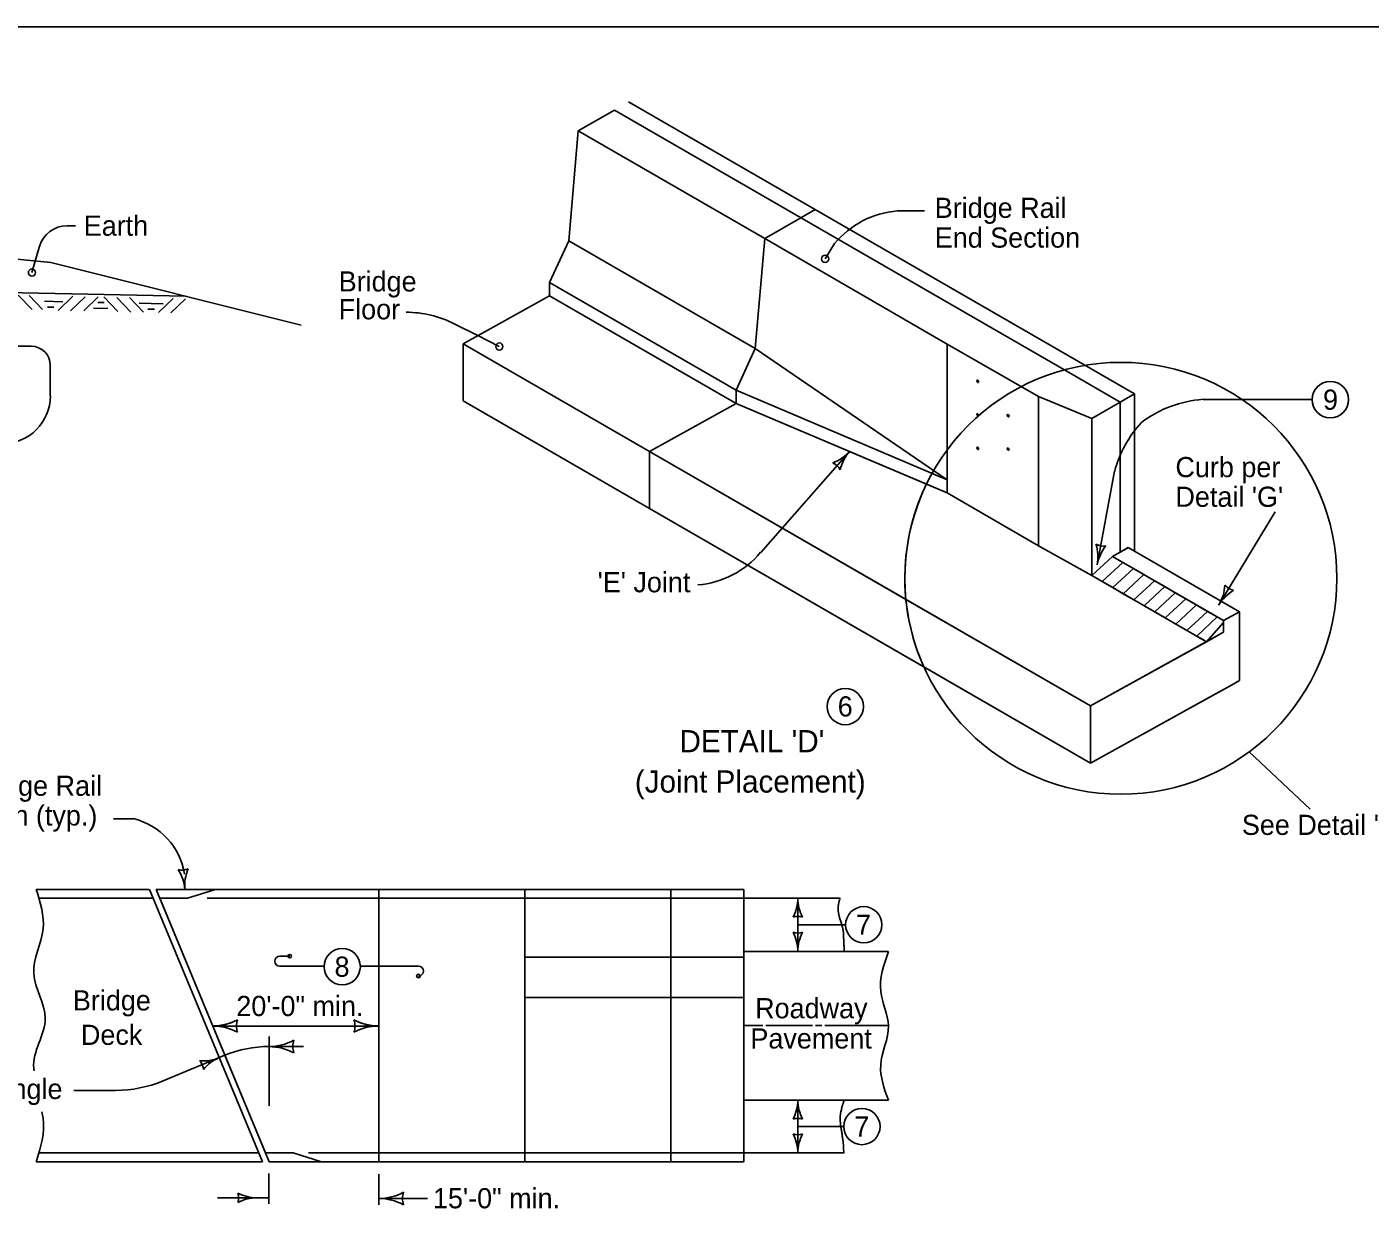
# Model space of a CAD drawing. Extents: x 10130 to 81668, y 5440 to 21644.
# Drawn here: x 18491 to 19823, y 6374 to 7554 of the extents above; entities that cross this region are included whole.
import ezdxf

# ---------------------------------------------------------------- set-up
doc = ezdxf.new("R2010")
doc.units = 0
for name, color, linetype in [('Cell', 7, 'Continuous'), ('dsnCellElements', 7, 'Continuous'), ('dsnStdBlockModified', 7, 'Continuous'), ('dsnStdBlockNotModified', 7, 'Continuous'), ('dsnStdBorder', 7, 'Continuous'), ('Level 5', 7, 'Continuous')]:
    doc.layers.add(name, color=color, linetype=linetype)

msp = doc.modelspace()

# ---------------------------------------------------------------- linework, layer by layer
at = {"layer": 'Cell'}
msp.add_lwpolyline([(17403.2, 7554.1), (20538.2, 7554.1), (20538.2, 5544.1), (17403.2, 5544.1)], close=True, dxfattribs=at)
at = {"layer": 'dsnCellElements'}
for centre in [(19282.5, 7324), (18495.9, 7310.4), (18959.4, 7237)]:
    msp.add_circle(centre, 3.54, dxfattribs=at)
at = {"layer": 'dsnStdBlockModified'}
for p, q in [((19129.6, 6689.8), (18984.7, 6689.8)), ((18984.7, 6689.8), (18984.7, 6631.2)), ((19129.6, 6631.2), (19129.6, 6689.8)), ((19202, 6689.8), (19129.6, 6689.8)), ((19129.6, 6689.8), (19129.6, 6631.2)), ((19202, 6631.2), (19202, 6689.8)), ((19129.6, 6631.2), (18984.7, 6631.2)), ((18984.7, 6631.2), (18984.7, 6591.2)), ((18984.7, 6631.2), (19129.6, 6631.2)), ((19129.6, 6591.2), (19129.6, 6631.2)), ((19129.6, 6631.2), (19129.6, 6631.2)), ((19202, 6631.2), (19129.6, 6631.2)), ((19129.6, 6631.2), (19129.6, 6591.2)), ((19129.6, 6631.2), (19202, 6631.2)), ((19202, 6591.2), (19202, 6631.2)), ((18984.7, 6591.2), (18984.7, 6437)), ((18984.7, 6591.2), (19129.6, 6591.2)), ((19129.6, 6437), (19129.6, 6591.2)), ((19129.6, 6591.2), (19129.6, 6437)), ((19202, 6591.2), (19129.6, 6591.2)), ((19129.6, 6591.2), (19202, 6591.2)), ((19202, 6437), (19202, 6591.2)), ((18984.7, 6437), (19129.6, 6437)), ((19129.6, 6437), (19202, 6437))]:
    msp.add_line(p, q, dxfattribs=at)
for points in [[(18839.8, 6698.5), (18984.7, 6698.5), (18984.7, 6689.8), (18864.7, 6689.8), (18839.8, 6689.8)], [(19129.6, 6698.4), (19129.6, 6689.8), (18984.7, 6689.8), (18984.7, 6698.5)], [(19202, 6698.4), (19202, 6689.8), (19129.6, 6689.8), (19129.6, 6698.4)], [(18984.7, 6428.1), (18839.8, 6428.1), (18839.8, 6437), (18847, 6437), (18890.3, 6437), (18937.9, 6437), (18984.7, 6436.9)], [(18984.7, 6428.1), (18984.7, 6437), (19129.6, 6437), (19129.6, 6428.1)], [(19202, 6428.1), (19129.6, 6428.1), (19129.6, 6437), (19202, 6437)]]:
    msp.add_lwpolyline(points, close=True, dxfattribs=at)
msp.add_lwpolyline([(19129.6, 6591.2), (19129.6, 6591.2), (18984.7, 6591.2)], dxfattribs=at)
at = {"layer": 'dsnStdBlockNotModified'}
for centre in [(18751.5, 6632.2), (18879.2, 6612.5)]:
    msp.add_circle(centre, 1.78, dxfattribs=at)
for centre, radius, start, end in [((19275.1, 7161.3), 42.5, 290.5435, 318.616), ((19338.9, 7105.1), 42.5, 138.616, 166.6885), ((19283.5, 7106.4), 16.4, 30.8827, 66.3494), ((19558.9, 7055.5), 16.4, 241.782, 277.2487), ((19510.6, 7028.2), 42.5, 349.5153, 17.5878), ((19594.2, 7012.8), 42.5, 141.4428, 169.5153), ((19636.5, 7002.7), 42.5, 328.7108, 356.7833), ((19709.1, 6958.5), 42.5, 120.6383, 148.7108), ((19691.3, 7011.1), 16.4, 220.9775, 256.4442), ((18644.8, 6734), 16.4, 256.6331, 292.0998), ((18605.1, 6695.2), 42.5, 4.3665, 32.439), ((18689.9, 6701.7), 42.5, 156.294, 184.3665)]:
    msp.add_arc(centre, radius, start, end, dxfattribs=at)
at = {"layer": 'dsnStdBorder'}
for p, q in [((19087.6, 7479.7), (19589.4, 7190)), ((19258.5, 7364.7), (19272.6, 7372.9)), ((19354, 7371.6), (19380.9, 7371.6)), ((18539.1, 7356.8), (18530.7, 7356.8)), ((19213.2, 7234.9), (19028.2, 7341.7)), ((18402.4, 7331.6), (18514.7, 7320.4)), ((18503.5, 7336.4), (18495.9, 7310.4)), ((19282.5, 7324), (19291.8, 7339.2)), ((18514.7, 7320.4), (18763, 7258.3)), ((19009.3, 7300.4), (19009.3, 7287.3)), ((19194.3, 7193.6), (19009.3, 7300.4)), ((18470.5, 7290.5), (18648.4, 7287)), ((18482.2, 7288), (18496.1, 7273.6)), ((18493.1, 7287.6), (18506.5, 7273.7)), ((18536.3, 7286.8), (18521.9, 7272.9)), ((18548.7, 7286.3), (18534.3, 7272.4)), ((18561.7, 7286.3), (18547.3, 7272.4)), ((18567.2, 7286.2), (18581, 7271.7)), ((18580.2, 7285.7), (18594, 7271.2)), ((18592.6, 7285.6), (18606.5, 7271.2)), ((18635.8, 7284.8), (18621.4, 7270.9)), ((18648.3, 7284.3), (18633.8, 7270.4)), ((18914.7, 7259.6), (18938.1, 7247.8)), ((18938.1, 7247.8), (18959.4, 7237)), ((18495.2, 7237.3), (18470.5, 7237.3)), ((19403.7, 7239.5), (19403.7, 7091.7)), ((18514.1, 7218.4), (18514.1, 7188)), ((19194.3, 7180.5), (19108.5, 7132.9)), ((19194.3, 7180.5), (19108.5, 7132.9)), ((19383, 7100.4), (19194.3, 7180.5)), ((19403.7, 7091.7), (19194.3, 7180.5)), ((19494.2, 7187.3), (19494.2, 7039.4)), ((19575.2, 7181.8), (19589.4, 7190)), ((19589.4, 7190), (19589.4, 7033.9)), ((19657.4, 7184.6), (19765.5, 7184.6)), ((19547, 7009.8), (19547, 7165.5)), ((19108.5, 7132.9), (19108.5, 7076.3)), ((19362.6, 6986.2), (19108.5, 7132.9)), ((19108.5, 7132.9), (19108.5, 7076.3)), ((19108.5, 7132.9), (19362.6, 6986.2)), ((19108.5, 7132.9), (19545.7, 6880.4)), ((19307, 7133.2), (19218.6, 7032.8)), ((19403.7, 7091.7), (19383, 7100.4)), ((19569.6, 7113.5), (19552.4, 7020.5)), ((19494.2, 7039.4), (19403.7, 7091.7)), ((19494.2, 7039.4), (19403.7, 7091.7)), ((19108.5, 7076.3), (19545.7, 6823.8)), ((19108.5, 7076.3), (19380.4, 6919.3)), ((19545.7, 6823.8), (19108.5, 7076.3)), ((19672.8, 6980.6), (19728.9, 7073)), ((19547, 7009.8), (19494.2, 7039.4)), ((19547, 7009.8), (19494.2, 7039.4)), ((19693.3, 6973.9), (19583.1, 7037.5)), ((19693.3, 6973.9), (19583.1, 7037.5)), ((19567.4, 7028.8), (19547, 7009.8)), ((19567.4, 7028.8), (19547, 7009.8)), ((19557.4, 7003.8), (19577.8, 7022.8)), ((19577.8, 7022.8), (19557.4, 7003.8)), ((19577.8, 7022.8), (19557.4, 7003.8)), ((19575.2, 7033.1), (19567.4, 7028.8)), ((19577.8, 7022.8), (19567.4, 7028.8)), ((19567.4, 7028.8), (19577.8, 7022.8)), ((19677.6, 6965.2), (19567.4, 7028.8)), ((19588.2, 7016.7), (19577.8, 7022.8)), ((19577.8, 7022.8), (19588.2, 7016.7)), ((19557.4, 7003.8), (19547, 7009.8)), ((19547, 7009.8), (19557.4, 7003.8)), ((19660.7, 6944.2), (19547, 7009.8)), ((19567.8, 6997.8), (19588.2, 7016.7)), ((19588.2, 7016.7), (19567.8, 6997.8)), ((19588.2, 7016.7), (19567.8, 6997.8)), ((19578.2, 6991.8), (19598.6, 7010.7)), ((19598.6, 7010.7), (19578.2, 6991.8)), ((19598.6, 7010.7), (19578.2, 6991.8)), ((19598.6, 7010.7), (19588.2, 7016.7)), ((19588.2, 7016.7), (19598.6, 7010.7)), ((19609, 7004.7), (19598.6, 7010.7)), ((19598.6, 7010.7), (19609, 7004.7)), ((19557.4, 7003.8), (19567.8, 6997.8)), ((19567.8, 6997.8), (19578.2, 6991.8)), ((19588.6, 6985.8), (19609, 7004.7)), ((19609, 7004.7), (19588.6, 6985.8)), ((19609, 7004.7), (19588.6, 6985.8)), ((19619.3, 6998.8), (19599.2, 6980.2)), ((19362.6, 6986.2), (19545.7, 6880.4)), ((19545.7, 6880.4), (19362.6, 6986.2)), ((19578.2, 6991.8), (19588.6, 6985.8)), ((19588.6, 6985.8), (19609.4, 6973.8)), ((19609.4, 6973.8), (19629.8, 6992.7)), ((19629.8, 6992.7), (19609.4, 6973.8)), ((19629.8, 6992.7), (19609.4, 6973.8)), ((19619.8, 6967.8), (19640.2, 6986.7)), ((19640.2, 6986.7), (19619.8, 6967.8)), ((19640.2, 6986.7), (19619.8, 6967.8)), ((19640.2, 6986.7), (19629.8, 6992.7)), ((19629.8, 6992.7), (19640.2, 6986.7)), ((19650.7, 6980.7), (19630.3, 6961.7)), ((19609.4, 6973.8), (19619.8, 6967.8)), ((19619.8, 6967.8), (19630.3, 6961.7)), ((19661.7, 6974.3), (19641.3, 6955.4)), ((19651, 6949.8), (19671.4, 6968.7)), ((19671.4, 6968.7), (19651, 6949.8)), ((19671.4, 6968.7), (19651, 6949.8)), ((19677.6, 6965.2), (19671.4, 6968.7)), ((19671.4, 6968.7), (19677.6, 6965.2)), ((19685.4, 6969.5), (19677.6, 6965.2)), ((19677.6, 6965.2), (19685.4, 6969.5)), ((19685.4, 6969.5), (19677.6, 6965.2)), ((19693.3, 6973.9), (19685.4, 6969.5)), ((19685.4, 6969.5), (19693.3, 6973.9)), ((19693.3, 6973.9), (19685.4, 6969.5)), ((19693.3, 6905.6), (19693.3, 6973.9)), ((19630.3, 6961.7), (19651, 6949.8)), ((19660.7, 6944.2), (19677.6, 6963.2)), ((19677.6, 6963.2), (19660.7, 6944.2)), ((19660.7, 6944.2), (19677.6, 6963.2)), ((19677.6, 6963.2), (19677.6, 6965.2)), ((19677.6, 6953.5), (19677.6, 6965.2)), ((19677.6, 6953.5), (19677.6, 6963.2)), ((19545.7, 6880.4), (19677.6, 6953.5)), ((19545.7, 6880.4), (19660.7, 6944.2)), ((19660.7, 6944.2), (19545.7, 6880.4)), ((19651, 6949.8), (19657.1, 6946.2)), ((19660.7, 6944.2), (19657.1, 6946.2)), ((19657.1, 6946.2), (19660.7, 6944.2)), ((19677.6, 6953.5), (19660.7, 6944.2)), ((19660.7, 6944.2), (19677.6, 6953.5)), ((19380.4, 6919.3), (19545.7, 6823.8)), ((19650.2, 6881.7), (19685.4, 6901.2)), ((19670.4, 6892.9), (19685.4, 6901.2)), ((19685.4, 6901.2), (19693.3, 6905.6)), ((19693.3, 6905.6), (19685.4, 6901.2)), ((19545.7, 6823.8), (19670.4, 6892.9)), ((19545.7, 6823.8), (19545.7, 6880.4)), ((19703.2, 6834.9), (19763.5, 6778.1)), ((18596.2, 6768.6), (18576.7, 6768.6)), ((18500.2, 6698.5), (18612.3, 6698.5)), ((18503, 6689.8), (18616, 6689.8)), ((18724.4, 6428.1), (18612.4, 6698.5)), ((18731.1, 6428.1), (18619.1, 6698.5)), ((18619.1, 6698.5), (18839.8, 6698.5)), ((18622.6, 6689.8), (18650.2, 6689.8)), ((18650.2, 6689.8), (18677.9, 6698.5)), ((18669.7, 6689.8), (19297.4, 6689.8)), ((18839.8, 6637), (18839.8, 6698.5)), ((18839.8, 6437), (18839.8, 6698.5)), ((18839.8, 6698.5), (19202, 6698.4)), ((18984.7, 6689.7), (18839.8, 6689.8)), ((18984.7, 6428.1), (18984.7, 6698.5)), ((19129.6, 6428.1), (19129.6, 6698.4)), ((19202, 6428.1), (19202, 6698.4)), ((19202, 6437), (19202, 6689.8)), ((19255.4, 6637), (19255.4, 6689.8)), ((19255.4, 6663.4), (19284.9, 6663.4)), ((19284.9, 6663.4), (19302.8, 6663.4)), ((19202, 6637), (19345.3, 6637)), ((18751.5, 6632.2), (18741.7, 6632.2)), ((18785.6, 6622.3), (18741.7, 6622.3)), ((18821.6, 6622.3), (18879.2, 6622.3)), ((18675.1, 6562.9), (18839.8, 6562.9)), ((18816.2, 6562.9), (18698.7, 6562.9)), ((18698.7, 6562.9), (18816.2, 6562.9)), ((18839.8, 6562.9), (18839.8, 6562.9)), ((18839.8, 6562.9), (18839.8, 6495)), ((18731.1, 6552.6), (18731.1, 6483.9)), ((18731.1, 6542.6), (18765.1, 6542.6)), ((18687.3, 6533.9), (18625.9, 6508.4)), ((18578.9, 6499.1), (18537.4, 6499.1)), ((18839.8, 6495), (18839.8, 6437)), ((18839.8, 6428.1), (18839.8, 6495)), ((19202, 6489.5), (19345.3, 6489.5)), ((19255.4, 6436.9), (19255.4, 6489.5)), ((19255.4, 6463.2), (19284.9, 6463.2)), ((19284.9, 6463.2), (19301, 6463.2)), ((18502.9, 6437), (18720.8, 6437)), ((18727.4, 6437), (18755, 6437)), ((18727.4, 6437), (18755, 6437)), ((18755, 6437), (18783.1, 6428.1)), ((18755, 6437), (18783.1, 6428.1)), ((18770.1, 6437), (19301.1, 6437)), ((18839.8, 6437), (18890.3, 6437)), ((18890.3, 6437), (18890.3, 6437)), ((18500.2, 6428.1), (18724.4, 6428.1)), ((18731.1, 6428.1), (18839.8, 6428.1)), ((18783.1, 6428.1), (18839.8, 6428.1)), ((18839.8, 6428.1), (19202, 6428.1)), ((18730.7, 6416.6), (18730.7, 6386.4)), ((18839.8, 6415.8), (18839.8, 6385.7)), ((18679.8, 6392.6), (18730.7, 6392.6)), ((18839.8, 6391.8), (18888.2, 6391.8))]:
    msp.add_line(p, q, dxfattribs=at)
for points in [[(19073.5, 7471.5), (19439.5, 7260.2), (19530, 7208), (19575.2, 7181.8), (19547, 7165.5), (19494.2, 7187.3), (19403.7, 7239.5), (19222.6, 7344.1), (19037.6, 7450.9)], [(19037.6, 7450.9), (19073.5, 7471.5)], [(19009.3, 7300.4), (19028.2, 7341.7), (19037.6, 7450.9)], [(19222.6, 7344.1), (19258.5, 7364.7)], [(19194.3, 7180.5), (19194.3, 7193.6), (19213.2, 7234.9), (19222.6, 7344.1)], [(19009.3, 7287.3), (18923.5, 7239.7)], [(19194.3, 7180.5), (19009.3, 7287.3)], [(18508.5, 7281.9), (18526.6, 7281.5)], [(18511.2, 7276), (18517.7, 7275.9)], [(18557.1, 7275), (18571.3, 7274.7)], [(18561.1, 7280.8), (18567.6, 7280.6)], [(18602.1, 7280), (18626.1, 7279.5)], [(18610.7, 7274), (18617.3, 7273.9)], [(18923.5, 7239.7), (19108.5, 7132.9)], [(18923.5, 7183.1), (18923.5, 7239.7)], [(19194.3, 7193.6), (19403.7, 7104.7), (19213.2, 7234.9)], [(19108.5, 7076.3), (18923.5, 7183.1)], [(19194.3, 7180.5), (19108.5, 7132.9)], [(19575.2, 7181.8), (19575.2, 7033.1)], [(19108.5, 7076.3), (19108.5, 7132.9)], [(19583.1, 7037.5), (19582.3, 7037), (19575.2, 7033.1)], [(19583.1, 7037.5), (19575.2, 7033.1)], [(19575.2, 7033.1), (19567.4, 7028.8)], [(19578.2, 6991.8), (19567.8, 6997.8), (19557.4, 7003.8)], [(19629.8, 6992.7), (19619.3, 6998.8), (19609, 7004.7)], [(19609, 7004.7), (19619.3, 6998.8), (19629.8, 6992.7)], [(19609.4, 6973.8), (19588.6, 6985.8), (19578.2, 6991.8)], [(19671.4, 6968.7), (19661.7, 6974.3), (19640.2, 6986.7)], [(19640.2, 6986.7), (19661.7, 6974.3), (19671.4, 6968.7)], [(19657.1, 6946.2), (19651, 6949.8), (19630.3, 6961.7), (19619.8, 6967.8), (19609.4, 6973.8)], [(19693.3, 6973.9), (19693.3, 6905.6)], [(19677.6, 6965.2), (19677.6, 6963.2), (19677.6, 6953.5)], [(19545.7, 6823.8), (19650.2, 6881.7), (19670.4, 6892.9)], [(18839, 6562.9), (18839.8, 6562.9), (18839.8, 6698.5), (18677.9, 6698.5), (18650.2, 6689.8), (18622.7, 6689.8), (18675.2, 6562.9), (18675.9, 6562.9)], [(18839.8, 6689.8), (18839.8, 6622.3), (18839.8, 6562.9)], [(18984.7, 6436.9), (18984.7, 6563.4), (18984.7, 6689.7)], [(18675.2, 6562.9), (18687.3, 6533.9), (18727.4, 6437)], [(18839.8, 6428.1), (18839.8, 6437), (18839.8, 6489.6), (18839.8, 6562.9)], [(18839.8, 6562.9), (18839.8, 6562.9)], [(19202, 6563.3), (19220.7, 6563.3)], [(19223.8, 6563.3), (19269.9, 6563.3)], [(19273, 6563.3), (19279.1, 6563.3)], [(19282.2, 6563.3), (19345.3, 6563.3)], [(18890.3, 6437), (18937.9, 6437), (18984.7, 6436.9)]]:
    msp.add_lwpolyline(points, dxfattribs=at)
for centre, radius in [((19575.8, 7007.1), 214.2), ((19783.5, 7184.3), 18), ((19302.5, 6879.8), 18), ((19320.8, 6663.4), 18), ((18803.6, 6621.8), 18), ((19319, 6463.2), 18)]:
    msp.add_circle(centre, radius, dxfattribs=at)
for centre, radius, start, end in [((19361.7, 7280.9), 91, 94.8409, 140.1467), ((18530.7, 7328.4), 28.4, 90, 163.739), ((18867, 7165.1), 105.9, 63.2177, 90), ((18495.2, 7218.4), 18.9, 0, 90), ((18466.9, 7188), 47.3, 270, 360), ((19666.3, 7067.5), 117.5, 94.3399, 126.627), ((19683, 7082.5), 117.5, 137.5971, 164.7195), ((19575.8, 7007.1), 214.2, 154.1687, 185.6063), ((19575.8, 7007.1), 214.2, 154.1687, 185.6063), ((19148.7, 7091.2), 91, 274.8409, 320.1467), ((19575.8, 7007.1), 214.2, 185.6063, 204.2018), ((19575.8, 7007.1), 214.2, 185.6063, 204.2018), ((18581.1, 6703.7), 66.7, 8.4828, 76.8823), ((19215.2, 6689.8), 40.2, 331.9275, 360), ((19295.6, 6689.8), 40.2, 180, 208.0725), ((19255.4, 6656.1), 15.5, 72.2666, 107.7334), ((19255.4, 6670.7), 15.5, 252.2666, 287.7333), ((19215.2, 6637), 40.2, 360, 28.0725), ((19295.6, 6637), 40.2, 151.9275, 180), ((18741.7, 6627.2), 4.92, 90, 270), ((18879.2, 6617.4), 4.92, 270, 90), ((18675.1, 6615.2), 52.2, 270, 298.0725), ((18675.1, 6615.2), 52.2, 270.8433, 298.0725), ((18718.9, 6562.9), 20.2, 162.2666, 197.7334), ((18718.9, 6562.9), 20.2, 162.2667, 179.9839), ((18796, 6562.9), 20.2, 342.2666, 17.7334), ((18839.8, 6615.2), 52.2, 241.9275, 270), ((18796, 6562.9), 20.2, 0.0161, 17.7334), ((18839.8, 6615.2), 52.2, 241.9275, 269.1567), ((18675.1, 6510.7), 52.2, 61.9275, 90), ((18675.1, 6510.7), 52.2, 61.9275, 89.8364), ((18718.9, 6562.9), 20.2, 179.9839, 197.7334), ((18839.8, 6510.7), 52.2, 90.0176, 118.0725), ((18796, 6562.9), 20.2, 342.2666, 0.0161), ((18839.8, 6510.7), 52.2, 90, 118.0725), ((18839.8, 6615.2), 52.2, 269.9824, 270), ((18731.1, 6428.1), 114.5, 90, 112.5), ((18731.1, 6594.8), 52.2, 270, 298.0725), ((18731.1, 6594.8), 52.2, 270, 298.0725), ((18731.1, 6490.3), 52.2, 61.9275, 90), ((18731.1, 6490.3), 52.2, 61.9275, 90), ((18774.9, 6542.6), 20.2, 162.2666, 197.7334), ((18774.9, 6542.6), 20.2, 162.2666, 197.7334), ((18666.2, 6568.6), 40.2, 264.4275, 292.5), ((18650.5, 6518.6), 15.5, 4.7666, 40.2333), ((18697, 6494.4), 40.2, 112.5, 140.5725), ((18578.9, 6622), 122.9, 270, 292.5), ((19215.2, 6489.5), 40.2, 331.9275, 360), ((19295.6, 6489.5), 40.2, 180, 208.0725), ((19255.4, 6455.8), 15.5, 72.2666, 107.7334), ((19255.4, 6470.6), 15.5, 252.2666, 287.7333), ((19215.2, 6436.9), 40.2, 360, 28.0725), ((19295.6, 6436.9), 40.2, 151.9275, 180), ((18850.1, 6437), 40.2, 359.9859, 360), ((18685.3, 6392.5), 15.5, 342.2666, 17.7334), ((18719, 6432.7), 40.2, 241.9275, 270), ((18839.8, 6444), 52.2, 270, 298.0725), ((18883.6, 6391.8), 20.2, 162.2666, 197.7334), ((18719, 6352.4), 40.2, 90, 118.0725), ((18839.8, 6339.6), 52.2, 61.9275, 90)]:
    msp.add_arc(centre, radius, start, end, dxfattribs=at)
for centre in [(19433.8, 7202.4), (19433.8, 7169.2), (19464, 7168.4), (19433.8, 7136), (19464, 7135.2)]:
    msp.add_ellipse(centre, major_axis=(0.67, -1.15), ratio=0.57735, dxfattribs=at)
for points in [[(18500.2, 6698.5), (18507, 6659.3), (18497.7, 6614.9), (18509.1, 6570.5), (18497.7, 6521), (18498, 6518.6)], [(19345.3, 6637), (19337.6, 6597.3), (19345.3, 6563.2), (19337.6, 6524), (19345.3, 6489.5)], [(18505.8, 6477.7), (18507, 6471.5), (18500.2, 6428.1)]]:
    msp.add_spline(points, degree=3, dxfattribs=at)
for points in [[(19297.4, 6689.8), (19297.2, 6689.3), (19297, 6688.8), (19296.9, 6688.3), (19296.7, 6687.8), (19296.6, 6687.3), (19296.5, 6686.8), (19296.2, 6685.8), (19296, 6684.8), (19295.8, 6683.8), (19295.6, 6682.8), (19295.5, 6681.8), (19295.5, 6680.8), (19295.4, 6680.3), (19295.4, 6679.8), (19295.4, 6679.3), (19295.4, 6678.8), (19295.4, 6678.3), (19295.5, 6677.8), (19295.5, 6676.9), (19295.6, 6675.9), (19295.8, 6675), (19296, 6674.1), (19296.1, 6673.1), (19296.4, 6672.2), (19296.9, 6670.3), (19297.5, 6668.4), (19298.1, 6666.5), (19298.6, 6664.7), (19299.2, 6662.8), (19299.7, 6660.9), (19300, 6659.9), (19300.2, 6659), (19300.3, 6658), (19300.5, 6657.1), (19300.6, 6656.1), (19300.6, 6655.1), (19300.7, 6653.6), (19300.8, 6652.1), (19300.9, 6650.6), (19300.9, 6649.1), (19301, 6647.6), (19301.1, 6646.1), (19301.2, 6644.6), (19301.2, 6643.1), (19301.3, 6641.5), (19301.4, 6640), (19301.4, 6638.5), (19301.5, 6637)], [(19301.5, 6489.5), (19301.1, 6488.6), (19300.8, 6487.8), (19300.6, 6486.9), (19300.3, 6486), (19300, 6485.1), (19299.7, 6484.3), (19299.2, 6482.5), (19298.8, 6480.8), (19298.4, 6479), (19297.9, 6476.3), (19297.5, 6473.7), (19297.5, 6471), (19297.5, 6470.6), (19297.5, 6470.1), (19297.5, 6469.7), (19297.5, 6469.2), (19297.5, 6468.8), (19297.5, 6468.4), (19297.6, 6467.4), (19297.7, 6466.4), (19297.8, 6465.4), (19297.9, 6464.4), (19298, 6463.4), (19298.1, 6462.4), (19298.5, 6460.5), (19298.8, 6458.5), (19299.1, 6456.5), (19299.4, 6454.5), (19299.7, 6452.6), (19300, 6450.6), (19300.2, 6449.6), (19300.3, 6448.6), (19300.4, 6447.6), (19300.5, 6446.6), (19300.6, 6445.6), (19300.6, 6444.6), (19300.8, 6442.1), (19300.9, 6439.5), (19301.1, 6436.9)]]:
    msp.add_open_spline(points, degree=3, dxfattribs=at)

# ---------------------------------------------------------------- texts
at = {"layer": 'dsnStdBlockModified'}
for s, height, p in [('Earth', 20, (18547.3, 7346.9)), ('6', 20, (19295, 6870)), ('(Joint Placement)', 22, (19093.8, 6794.5)), ('7', 20, (19313.2, 6653.4)), ('8', 20, (18796, 6611.8)), ('Bridge', 20, (18536.5, 6578.4)), ('20\'-0" min.', 20, (18698.6, 6572.8)), ('Roadway', 20, (19213.1, 6570.6)), ('Deck', 20, (18544.5, 6544.2)), ('Pavement', 20, (19208.4, 6540.6)), ('Skew Angle', 20, (18385, 6490.5)), ('7', 20, (19311.4, 6453.2)), ('15\'-0" min.', 20, (18893.6, 6382.1))]:
    msp.add_text(s, height=height, dxfattribs=at).set_placement(p)
at = {"layer": 'dsnStdBorder'}
for s, height, p in [('Bridge Rail ', 20, (19391.2, 7364.6)), ('End Section', 20, (19391.2, 7335.1)), ('Bridge', 20, (18800.1, 7291.6)), ('Floor', 20, (18800.1, 7264)), ('Curb per', 20, (19629.9, 7107.4)), ("Detail 'G'", 20, (19629.9, 7078)), ("'E' Joint", 20, (19056.9, 6993.2)), ("DETAIL 'D'", 22, (19138.1, 6834.5)), ('Bridge Rail', 20, (18434.6, 6791.3)), ('End Section (typ.)', 20, (18348.2, 6761.8)), ("See Detail 'E'", 20, (19695.8, 6752.5))]:
    msp.add_text(s, height=height, dxfattribs=at).set_placement(p)
at = {"layer": 'Level 5'}
msp.add_text('9', height=20, dxfattribs=at).set_placement((19776.3, 7174.3))

doc.saveas('drawing.dxf')
